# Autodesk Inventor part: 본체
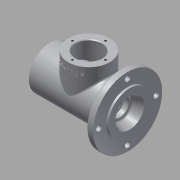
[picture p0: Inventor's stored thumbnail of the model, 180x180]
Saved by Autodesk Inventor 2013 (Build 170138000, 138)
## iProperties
Created: 2016-08
Part Number: 본체
Material: 알루미늄 6061
Document SubType Name: Modeling
Designer: Administrator
Density: 2.71 g/cm^3
Mass: 730.553 g
Surface Area: 615.603 cm^2
Volume: 269.577 cm^3
Author: Administrator
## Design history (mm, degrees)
sketch "스케치1"
  geometry: L1 (-56, 0)-(-56, 31); L2 (-56, 31)-(46, 31); L3 (46, 31)-(46, 50); L4 (46, 50)-(56, 50); L5 (59, 31)-(59, 0); L6 (59, 0)-(-56, 0); L7 (56, 50)-(56, 31); L8 (56, 31)-(59, 31); 1 further point
  constraints: 16 end point, 4 perpendicular, 3 parallel, 1 point on line, 1 vertical
  dimensions: "d0" = 56 distance from line of point (0, 0) L1; "d1" = 115 distance of L5.end L1.start; "d2" = 62 diameter of L2 L6; "d3" = 100 diameter of L4 L6; "d6" = 13 distance between parallel lines of L5 L3; "d7" = 3 distance of L7.end L5.start; "d8" = 62 diameter of L8 L6
revolve "회전2" sketch "스케치1" stored, may be unused: angle "d9" = 90 deg
sketch "스케치2"
  geometry: L1 (46, -31)-(46, 31) reference; L2 (-56, -31)-(-56, 31) reference; L3 (56, -50)-(56, 50) reference; L4 (46, -50)-(46, 50) reference; L5 (59, -31)-(59, 31) reference; L6 (56, -31)-(56, 31) reference; L7 (-56, 31)-(46, 31) reference; L8 (56, 31)-(59, 31) reference; L9 (46, 50)-(56, 50) reference; L10 (-56, -31)-(46, -31) reference; L11 (-47, 0)-(59, 0); L12 (-47, 0)-(-44, 0); L13 (-44, 0)-(-44, 24); L14 (-44, 24)-(-47, 24); L15 (-47, 24)-(-47, 0); L16 (-44, 0)-(-35, 0); L17 (-35, 0)-(-35, 20); L18 (-35, 20)-(-44, 20); L19 (-44, 20)-(-44, 0); L20 (-35, 0)-(-31.75, 0); L21 (-31.75, 0)-(-31.75, 17.5); L22 (-31.75, 17.5)-(-35, 17.5); L23 (-35, 17.5)-(-35, 0); L24 (-31.75, 0)-(-30, 0); L25 (-30, 0)-(-30, 18.5); L26 (-30, 18.5)-(-31.75, 18.5); L27 (-31.75, 18.5)-(-31.75, 0); L28 (-30, 0)-(-19, 0); L29 (-19, 0)-(-19, 17.5); L30 (-19, 17.5)-(-30, 17.5); L31 (-30, 17.5)-(-30, 0); L32 (-19, 0)-(19, 0); L33 (19, 0)-(19, 26); L34 (19, 26)-(-19, 26); L35 (-19, 26)-(-19, 0); L36 (19, 0)-(30, 0); L37 (30, 0)-(30, 17.5); L38 (30, 17.5)-(19, 17.5); L39 (19, 17.5)-(19, 0); L40 (30, 0)-(35, 0); L41 (35, 0)-(35, 16.5); L42 (35, 16.5)-(30, 16.5); L43 (30, 16.5)-(30, 0); L44 (35, 0)-(37.7, 0); L45 (37.7, 0)-(37.7, 10); L46 (37.7, 10)-(35, 10); L47 (35, 10)-(35, 0); L48 (37.7, 0)-(45, 0); L49 (45, 0)-(45, 12.5); L50 (45, 12.5)-(37.7, 12.5); L51 (37.7, 12.5)-(37.7, 0); L52 (45, 12.5)-(45, 16); L53 (45, 16)-(59, 21); L54 (0, 0)-(0, -50); L55 (44.3, 12.5)-(45, 12.904); L56 (59, 0)-(59, 21); 1 further point
  constraints: 92 end point, 23 parallel, 10 horizontal, 10 perpendicular, 5 point on line, 2 midpoint, 1 collinear
  dimensions: "d10" = 14 distance from line of L5 L52.end; "d11" = 2.7 distance of L45.end L46.end; "d12" = 7.3 distance of L49.end L50.end; "d13" = 5 distance of L41.end L42.end; "d14" = 38 distance of L33.end L34.end; "d16" = 3 distance of L13.end L14.end; "d17" = 12 distance between parallel lines of L2 L19; "d18" = 21 distance between parallel lines of L17 L2; "d20" = 1.75 distance of L25.end L26.end; "d21" = 26 distance between parallel lines of L2 L31; "d23" = 42 diameter of L53.end L11; "d24" = 32 diameter of L52.end L11; "d25" = 25 diameter of L50 L11; "d26" = 20 diameter of L46 L11; "d27" = 33 diameter of L42 L11; "d28" = 35 diameter of L38 L11; "d29" = 35 diameter of L30 L11; "d30" = 52 diameter of L34 L11; "d31" = 37 diameter of L26 L11; "d32" = 35 diameter of L22 L11; "d33" = 40 diameter of L18 L11; "d34" = 48 diameter of L14 L11; "d35" = 30 deg angle of L50 L55; "d36" = 0.7 distance of L49.end L55.start
revolve "회전3" sketch "스케치2" stored, may be unused: angle "d37" = 90 deg
sketch "스케치3"
  geometry: L1 (56, -50)-(56, 50) reference; L2 (46, -50)-(46, 50) reference; L3 (59, -31)-(59, 31) reference; L4 (56, -31)-(56, 31) reference; L5 (46, -31)-(46, 31) reference; L6 (-56, -31)-(-56, 31) reference; L7 (45, 12.904)-(45, -12.904) reference; L8 (45, 12.904)-(44.3, 12.5) reference; L9 (0, 0)-(59, 0); L10 (59, 0)-(59, 21); L11 (45, 0)-(45, 16); L12 (45, 16)-(59, 21)
  constraints: 8 end point, 2 point on line, 1 midpoint, 1 parallel, 1 perpendicular
  dimensions: "d38" = 42 diameter of L10.end L9; "d40" = 32 diameter of L11.end L9; "d41" = 14 distance between parallel lines of L10 L11
revolve "회전4" sketch "스케치3" stored, may be unused: angle "d42" = 90 deg
node "작업 평면1"
sketch "스케치4"
  geometry: C1 r 30 at (0, 0); 1 further point
  constraints: 1 centre point, 1 coincident
  dimensions: "d44" = 60 diameter of C1
extrude "돌출1" join sketch "스케치4" stored distance "d45" = 10; taper "d46" = 0 deg
hole "구멍1" diameter "d49" = 38; stored, may be unused: countersink angle "d53" = 90 deg, drill point angle "d55" = 0 deg; dims "d47" = 10, "d48" = 10, "d50" = 6, "d51" = 4, "d52" = 2, "d54" = 8
hole "구멍2" diameter "d58" = 40.376; stored, may be unused: countersink angle "d62" = 90 deg, drill point angle "d64" = 0 deg; dims "d56" = 10, "d57" = 10, "d59" = 9, "d60" = 4, "d61" = 2, "d63" = 9
chamfer "모따기1" distance "d65" = 1; stored, may be unused: second distance "d66" = 2, angle "d67" = 45 deg
fillet "모깎기1" dims "d68" = 0.3
fillet "모깎기2" dims "d69" = 3
sketch "스케치5" dims "d70" = 83
  geometry: L1 (0, 0)-(0, 41.5); C1 r 31 at (0, 0) reference; C2 r 50 at (0, 0) reference; 5 further points
  constraints: 2 coincident, 2 end point, 1 vertical, 1 vertical alignment, 7 other
  dimensions: "d73" = 360 deg dimension on L1.start point (0, 41.5) (derived)
hole "구멍3" sketch "스케치5" at (0, 41.5), (-41.5, 0), (0, -41.5), (41.5, 0) diameter "d75" = 8; stored, may be unused: countersink angle "d79" = 90 deg, drill point angle "d81" = 0 deg; dims "d76" = 9, "d77" = 4, "d78" = 2, "d80" = 9
sketch "스케치6" dims "d82" = 48
  geometry: L1 (0, 0)-(0, 24); 5 further points
  constraints: 2 coincident, 2 end point, 1 vertical, 1 vertical alignment, 7 other
  dimensions: "d85" = 360 deg dimension on L1.start point (0, 24) (derived)
hole "구멍4" sketch "스케치6" at (0, 24), (-24, 0), (0, -24), (24, 0) diameter "d87" = 3.242; stored, may be unused: countersink angle "d91" = 90 deg, drill point angle "d93" = 118 deg; dims "d88" = 8, "d89" = 4, "d90" = 2, "d92" = 10
node "작업 평면2"
sketch "스케치7"
  geometry: L1 (-20.739, -6.998)-(20.739, -6.998); L2 (20.739, -6.998)-(20.739, -13.002); L3 (20.739, -13.002)-(-20.739, -13.002); L4 (-20.739, -13.002)-(-20.739, -6.998); L5 (0, -6.998)-(0, -13.002); L6 (-20.739, -10)-(20.739, -10); L7 (-30, 0)-(30, 0) reference; L8 (-56, -80)-(-56, -18) reference; 1 further point
  constraints: 4 end point, 4 midpoint, 2 other
  dimensions: "d94" = 10 distance between parallel lines of L6 L7; "d95" = 56 distance from line of L5.start L8
feature "엠보싱1" sketch "스케치7" dims "d0" = 56, "d1" = 115, "d2" = 62, "d3" = 100, "d6" = 13, "d7" = 3, "d8" = 62, "d96" = 0.5, "d97" = 0
node "솔리드2"
node "투영된 루프1"
node "투영된 루프2"
node "투영된 루프3"
node "투영된 루프4"
node "투영된 루프5"
node "투영된 루프6"
node "투영된 루프7"
other parameters: "d43" = 49
